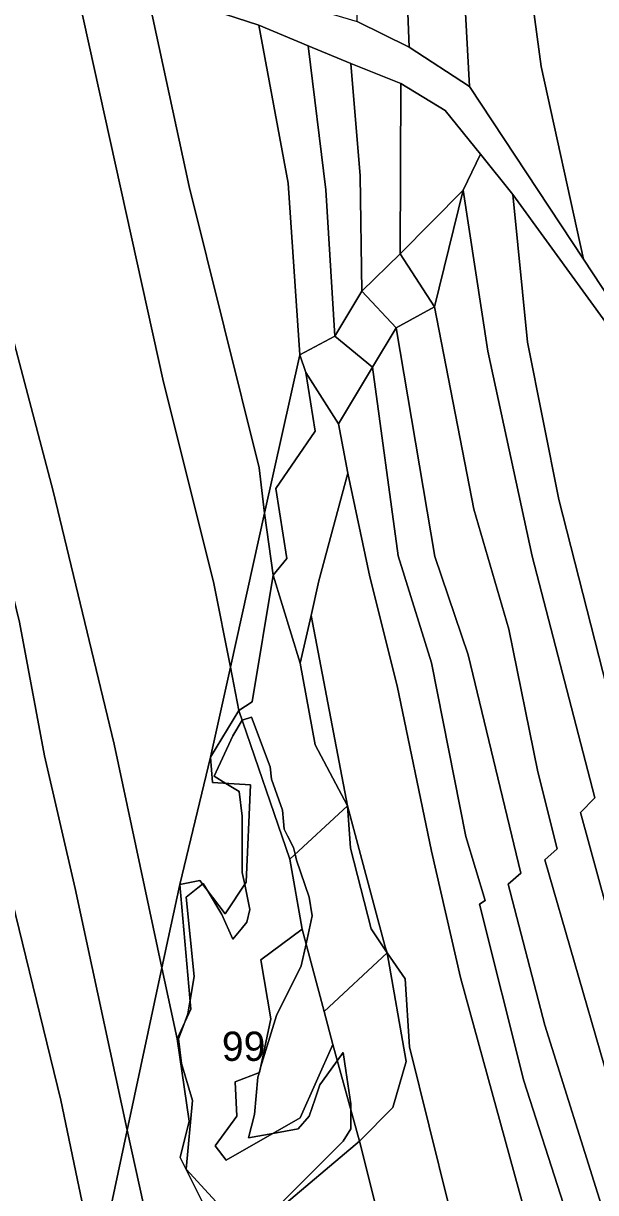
# Model space of a CAD drawing. Extents: x -502026 to -497664, y -1143484 to -1138019.
# Drawn here: x -499377.2 to -499220.8, y -1139831.7 to -1139511.9 of the extents above; entities that cross this region are included whole.
import ezdxf

# ---------------------------------------------------------------- set-up
doc = ezdxf.new("R2010")
doc.units = 0
for name, color, linetype in [('43', 7, 'Continuous'), ('55', 7, 'Continuous'), ('62', 7, 'Continuous'), ('7', 7, 'Continuous')]:
    doc.layers.add(name, color=color, linetype=linetype)

msp = doc.modelspace()

# ---------------------------------------------------------------- linework, layer by layer
at = {"layer": '43'}
msp.add_lwpolyline([(-499291.07, -1139621.36), (-499288.49, -1139634.86), (-499296.45, -1139664.36), (-499298.58, -1139673.8), (-499301.53, -1139686.89), (-499308.96, -1139662.77), (-499305.21, -1139658.22), (-499308.24, -1139639.1), (-499297.44, -1139623.4), (-499300.02, -1139607.4)], close=True, dxfattribs=at)
msp.add_lwpolyline([(-499326.63, -1139837.6), (-499334.36, -1139822.12), (-499331.93, -1139812.11), (-499335.19, -1139789.66), (-499331.44, -1139781.54), (-499334.47, -1139747.41), (-499329.02, -1139746.35), (-499322.04, -1139755.45), (-499316.28, -1139746.81), (-499315.1, -1139720.18), (-499325.49, -1139719.5), (-499326.1, -1139712.6), (-499318.29, -1139699.78), (-499304.37, -1139740.5), (-499301.04, -1139759.66), (-499312.34, -1139768.04), (-499309.61, -1139784.12), (-499312.64, -1139798.84), (-499319.31, -1139801.42), (-499318.86, -1139810.82), (-499324.77, -1139818.86), (-499321.74, -1139822.81), (-499301.57, -1139811.28), (-499292.61, -1139791.22), (-499285.35, -1139817.65), (-499308.24, -1139836.91)], dxfattribs=at)
at = {"layer": '55'}
for points in [[(-499585.34, -1139288.14), (-499562.08, -1139301.27), (-499548.14, -1139313.44), (-499534.96, -1139324.94), (-499524.3, -1139335.07), (-499512.1, -1139346.68), (-499502.1, -1139356.19), (-499492.77, -1139362.7), (-499462.72, -1139386.25), (-499432.97, -1139412.16), (-499404.85, -1139438.08), (-499385.31, -1139457.33), (-499365.03, -1139478.21), (-499347.12, -1139489.91), (-499325.24, -1139498.25), (-499309.82, -1139504.13), (-499296.4, -1139508.21), (-499285.99, -1139511.38), (-499271.78, -1139518.34), (-499255.2, -1139529.15), (-499224.08, -1139576.34), (-499199.1, -1139614.24)], [(-499215.82, -1139596.68), (-499243.36, -1139558.62), (-499252.2, -1139547.66), (-499261.86, -1139535.67), (-499274.05, -1139528.26), (-499287.66, -1139522.83), (-499299.35, -1139517.96), (-499312.87, -1139512.33), (-499343.57, -1139502.35), (-499365.18, -1139490.95), (-499392.27, -1139462.22), (-499414.47, -1139436.01), (-499437.56, -1139413.79), (-499462.13, -1139392.32), (-499482.26, -1139375.44), (-499508.76, -1139357.08), (-499525.43, -1139342.47), (-499537.48, -1139331.9), (-499550.21, -1139319.02), (-499569.54, -1139301.4), (-499573.6, -1139299.19), (-499583.04, -1139294.07)]]:
    msp.add_lwpolyline(points, dxfattribs=at)
for points in [[(-499300.02, -1139607.4), (-499297.44, -1139623.4), (-499308.24, -1139639.1), (-499305.21, -1139658.22), (-499308.96, -1139662.77), (-499311.29, -1139645.86), (-499301.68, -1139602.55)], [(-499308.96, -1139662.77), (-499314.65, -1139697.43), (-499318.29, -1139699.78), (-499320.64, -1139687.98), (-499311.29, -1139645.86)], [(-499301.53, -1139686.89), (-499297.4, -1139709.19), (-499288.62, -1139725.89), (-499304.37, -1139740.5), (-499318.29, -1139699.78), (-499314.65, -1139697.43), (-499308.96, -1139662.77)], [(-499288.62, -1139725.89), (-499297.4, -1139709.19), (-499301.53, -1139686.89), (-499298.58, -1139673.8)], [(-499318.29, -1139699.78), (-499326.1, -1139712.6), (-499320.64, -1139687.98)], [(-499334.47, -1139747.41), (-499326.1, -1139712.6), (-499325.49, -1139719.5), (-499315.1, -1139720.18), (-499316.28, -1139746.81), (-499322.04, -1139755.45), (-499329.02, -1139746.35)], [(-499277.78, -1139766.14), (-499294.97, -1139782.14), (-499301.04, -1139759.66), (-499304.37, -1139740.5), (-499288.62, -1139725.89), (-499287.79, -1139737.48), (-499282.13, -1139759.56)], [(-499277.78, -1139766.14), (-499282.13, -1139759.56), (-499287.79, -1139737.48), (-499288.62, -1139725.89), (-499278.33, -1139764.48)], [(-499335.19, -1139789.66), (-499339.35, -1139770.23), (-499334.47, -1139747.41), (-499331.44, -1139781.54)], [(-499294.97, -1139782.14), (-499292.61, -1139791.22), (-499301.57, -1139811.28), (-499321.74, -1139822.81), (-499324.77, -1139818.86), (-499318.86, -1139810.82), (-499319.31, -1139801.42), (-499312.64, -1139798.84), (-499309.61, -1139784.12), (-499312.34, -1139768.04), (-499301.04, -1139759.66)], [(-499285.35, -1139817.65), (-499292.61, -1139791.22), (-499294.97, -1139782.14), (-499277.78, -1139766.14), (-499272.53, -1139795.8), (-499276.17, -1139808.39)], [(-499335.19, -1139789.66), (-499331.93, -1139812.11), (-499334.36, -1139822.12), (-499326.63, -1139837.6), (-499337.17, -1139850.27), (-499344.29, -1139835.32), (-499348.85, -1139814.64), (-499339.35, -1139770.23)], [(-499344.29, -1139835.32), (-499344.29, -1139851.25), (-499355.29, -1139853.26), (-499357.18, -1139853.6), (-499348.85, -1139814.64)]]:
    msp.add_lwpolyline(points, close=True, dxfattribs=at)
at = {"layer": '62'}
for points in [[(-499306.78, -1139834.62), (-499289.78, -1139817.62), (-499287.66, -1139814.25), (-499287.66, -1139809.25), (-499287.66, -1139807.37), (-499289.03, -1139798.29), (-499289.78, -1139793.37), (-499291.4, -1139795.63), (-499293.07, -1139797.95), (-499296.16, -1139802.25), (-499297.48, -1139806.03), (-499299.12, -1139810.75), (-499302.09, -1139814.25), (-499308.98, -1139815.52), (-499315.69, -1139816.75), (-499314, -1139810.37), (-499313.16, -1139800.12), (-499312.98, -1139799.55), (-499312.78, -1139798.9), (-499312.5, -1139797.94), (-499312.37, -1139797.51), (-499308.06, -1139783.25), (-499301.25, -1139769.62), (-499299.95, -1139763.68), (-499298.28, -1139756), (-499299.12, -1139750.87), (-499302.53, -1139740.75), (-499302.92, -1139739.15), (-499303.37, -1139737.25), (-499304.98, -1139734.12), (-499305.94, -1139732.25), (-499306.1, -1139730.17), (-499306.34, -1139727.12), (-499309.34, -1139718.62), (-499309.75, -1139715.25), (-499314.84, -1139701.62), (-499317.37, -1139702.48), (-499319.94, -1139706.75), (-499325.06, -1139717.75), (-499321.88, -1139719.74), (-499318.25, -1139722), (-499317.41, -1139728.75), (-499317.41, -1139744.12), (-499316.71, -1139747.45), (-499315.28, -1139754.25), (-499316.12, -1139757.75), (-499317.7, -1139759.66), (-499319.94, -1139762.37), (-499322.94, -1139755.62), (-499326.62, -1139749.48), (-499328.03, -1139747.12), (-499328.27, -1139747.32), (-499329.55, -1139748.35), (-499332.69, -1139750.87), (-499330.56, -1139772.62), (-499331.66, -1139779.08), (-499332.28, -1139782.75), (-499333.39, -1139785.76), (-499334.81, -1139789.62), (-499333.97, -1139796.37), (-499331, -1139806.5), (-499332.69, -1139825.25), (-499314.44, -1139845.25)], [(-499314.44, -1139845.25), (-499332.69, -1139825.25), (-499331, -1139806.5), (-499333.97, -1139796.37), (-499334.81, -1139789.62), (-499333.39, -1139785.76), (-499332.28, -1139782.75), (-499331.66, -1139779.08), (-499330.56, -1139772.62), (-499332.69, -1139750.87), (-499329.55, -1139748.35), (-499328.27, -1139747.32), (-499328.03, -1139747.12), (-499326.62, -1139749.48), (-499322.94, -1139755.62), (-499319.94, -1139762.37), (-499317.7, -1139759.66), (-499316.12, -1139757.75), (-499315.28, -1139754.25), (-499316.71, -1139747.45), (-499317.41, -1139744.12), (-499317.41, -1139728.75), (-499318.25, -1139722), (-499321.88, -1139719.74), (-499325.06, -1139717.75), (-499319.94, -1139706.75), (-499317.37, -1139702.48), (-499314.84, -1139701.62), (-499309.75, -1139715.25), (-499309.34, -1139718.62), (-499306.34, -1139727.12), (-499306.1, -1139730.17), (-499305.94, -1139732.25), (-499304.98, -1139734.12), (-499303.37, -1139737.25), (-499302.92, -1139739.15), (-499302.53, -1139740.75), (-499299.12, -1139750.87), (-499298.28, -1139756), (-499299.95, -1139763.68), (-499301.25, -1139769.62), (-499308.06, -1139783.25), (-499312.37, -1139797.51), (-499312.5, -1139797.94), (-499312.78, -1139798.9), (-499312.98, -1139799.55), (-499313.16, -1139800.12), (-499314, -1139810.37), (-499315.69, -1139816.75), (-499308.98, -1139815.52), (-499302.09, -1139814.25), (-499299.12, -1139810.75), (-499297.48, -1139806.03), (-499296.16, -1139802.25), (-499293.07, -1139797.95), (-499291.4, -1139795.63), (-499289.78, -1139793.37), (-499289.03, -1139798.29), (-499287.66, -1139807.37), (-499287.66, -1139809.25), (-499287.66, -1139814.25), (-499289.78, -1139817.62), (-499306.78, -1139834.62)]]:
    msp.add_lwpolyline(points, dxfattribs=at)
at = {"layer": '7'}
for points in [[(-499184.44, -1139632.22), (-499199.1, -1139614.24), (-499224.08, -1139576.34), (-499235.64, -1139523.61), (-499238.66, -1139501.23), (-499241.43, -1139463.52), (-499248.42, -1139418.44), (-499264.05, -1139355.76), (-499283.41, -1139271.78), (-499295.8, -1139226.21), (-499280.37, -1139217.41), (-499264.5, -1139279.38), (-499232, -1139415.17), (-499219.14, -1139483.23), (-499192.99, -1139592.49)], [(-499224.08, -1139576.34), (-499255.2, -1139529.15), (-499257.54, -1139487.26), (-499262.31, -1139442.14), (-499279.52, -1139375.35), (-499296.97, -1139280.67), (-499308.44, -1139229.47), (-499295.8, -1139226.21), (-499283.41, -1139271.78), (-499264.05, -1139355.76), (-499248.42, -1139418.44), (-499241.43, -1139463.52), (-499238.66, -1139501.23), (-499235.64, -1139523.61)], [(-499255.2, -1139529.15), (-499271.78, -1139518.34), (-499272.89, -1139487.91), (-499275.59, -1139453.77), (-499280.27, -1139423.8), (-499287.25, -1139390.3), (-499300.27, -1139320.29), (-499320.87, -1139232.68), (-499308.44, -1139229.47), (-499296.97, -1139280.67), (-499279.52, -1139375.35), (-499262.31, -1139442.14), (-499257.54, -1139487.26)], [(-499271.78, -1139518.34), (-499285.99, -1139511.38), (-499286.22, -1139486.08), (-499289.95, -1139431.87), (-499303.88, -1139361.24), (-499323.12, -1139270.86), (-499332.52, -1139235.5), (-499320.87, -1139232.68), (-499300.27, -1139320.29), (-499287.25, -1139390.3), (-499280.27, -1139423.8), (-499275.59, -1139453.77), (-499272.89, -1139487.91)], [(-499462.13, -1139392.32), (-499452.18, -1139431.77), (-499430, -1139542.05), (-499408.7, -1139631.01), (-499398.52, -1139677.52), (-499366.99, -1139806.44), (-499357.18, -1139853.6), (-499365.9, -1139907.16), (-499375.64, -1139869.1), (-499386.86, -1139810.63), (-499402.82, -1139746.67), (-499404.07, -1139741.68), (-499434.09, -1139621.39), (-499461.83, -1139476.75), (-499476.3, -1139410.22), (-499482.26, -1139375.44)], [(-499437.56, -1139413.79), (-499408.51, -1139551.73), (-499378.3, -1139675.67), (-499371.42, -1139712.23), (-499363.06, -1139748.52), (-499348.85, -1139814.64), (-499357.18, -1139853.6), (-499366.99, -1139806.44), (-499398.52, -1139677.52), (-499408.7, -1139631.01), (-499430, -1139542.05), (-499452.18, -1139431.77), (-499462.13, -1139392.32)], [(-499414.47, -1139436.01), (-499408.53, -1139458.9), (-499399.6, -1139514.37), (-499386.26, -1139575.02), (-499369.1, -1139639.83), (-499352.45, -1139709.04), (-499339.35, -1139770.23), (-499348.85, -1139814.64), (-499363.06, -1139748.52), (-499371.42, -1139712.23), (-499378.3, -1139675.67), (-499408.51, -1139551.73), (-499437.56, -1139413.79)], [(-499365.18, -1139490.95), (-499338.95, -1139609.98), (-499325.28, -1139664.66), (-499320.64, -1139687.98), (-499326.1, -1139712.6), (-499334.47, -1139747.41), (-499339.35, -1139770.23), (-499352.45, -1139709.04), (-499369.1, -1139639.83), (-499386.26, -1139575.02), (-499399.6, -1139514.37), (-499408.53, -1139458.9), (-499414.47, -1139436.01), (-499392.27, -1139462.22)], [(-499343.57, -1139502.35), (-499331.88, -1139556.45), (-499312.72, -1139633.39), (-499311.29, -1139645.86), (-499320.64, -1139687.98), (-499325.28, -1139664.66), (-499338.95, -1139609.98), (-499365.18, -1139490.95)], [(-499312.87, -1139512.33), (-499304.83, -1139555.53), (-499301.68, -1139602.55), (-499311.29, -1139645.86), (-499312.72, -1139633.39), (-499331.88, -1139556.45), (-499343.57, -1139502.35)], [(-499299.35, -1139517.96), (-499294.52, -1139557.38), (-499292.09, -1139597.4), (-499301.68, -1139602.55), (-499304.83, -1139555.53), (-499312.87, -1139512.33)], [(-499287.66, -1139522.83), (-499285.12, -1139553.59), (-499284.66, -1139585.11), (-499292.09, -1139597.4), (-499294.52, -1139557.38), (-499299.35, -1139517.96)], [(-499274.05, -1139528.26), (-499274.16, -1139574.86), (-499284.66, -1139585.11), (-499285.12, -1139553.59), (-499287.66, -1139522.83)], [(-499252.2, -1139547.66), (-499256.96, -1139557.49), (-499274.16, -1139574.86), (-499274.05, -1139528.26), (-499261.86, -1139535.67)], [(-499243.36, -1139558.62), (-499239.42, -1139599.08), (-499230.83, -1139642.06), (-499214.44, -1139706.36), (-499209.67, -1139716.86), (-499209.83, -1139727.05), (-499201.88, -1139768.54), (-499185.97, -1139833.48), (-499171.61, -1139880.27), (-499160.9, -1139922.71), (-499128.96, -1140056.4), (-499142.54, -1140055.34), (-499172.92, -1139921.27), (-499194.67, -1139838.33), (-499224.86, -1139727.73), (-499220.97, -1139723.67), (-499238.15, -1139657.58), (-499250.24, -1139601.55), (-499256.96, -1139557.49), (-499252.2, -1139547.66)], [(-499264.84, -1139589.42), (-499274.16, -1139574.86), (-499256.96, -1139557.49)], [(-499142.54, -1140055.34), (-499154.67, -1140054.94), (-499164.65, -1140012.6), (-499171.01, -1139974.56), (-499179.92, -1139940.65), (-499186.73, -1139912.32), (-499196.49, -1139877.28), (-499202.19, -1139853.04), (-499234.65, -1139740.66), (-499231.31, -1139737.63), (-499236.56, -1139716.62), (-499244.51, -1139677.55), (-499254.06, -1139644.76), (-499264.84, -1139589.42), (-499256.96, -1139557.49), (-499250.24, -1139601.55), (-499238.15, -1139657.58), (-499220.97, -1139723.67), (-499224.86, -1139727.73), (-499194.67, -1139838.33), (-499172.92, -1139921.27)], [(-499215.82, -1139596.68), (-499208.46, -1139633.77), (-499197.99, -1139677.85), (-499190.23, -1139708.81), (-499169.74, -1139776.79), (-499160.99, -1139813.35), (-499148.42, -1139858.6), (-499137.92, -1139908.57), (-499110.87, -1140004.1), (-499100.75, -1140060.46), (-499128.96, -1140056.4), (-499160.9, -1139922.71), (-499171.61, -1139880.27), (-499185.97, -1139833.48), (-499201.88, -1139768.54), (-499209.83, -1139727.05), (-499209.67, -1139716.86), (-499214.44, -1139706.36), (-499230.83, -1139642.06), (-499239.42, -1139599.08), (-499243.36, -1139558.62)], [(-499264.84, -1139589.42), (-499275.3, -1139595.11), (-499284.66, -1139585.11), (-499274.16, -1139574.86)], [(-499275.3, -1139595.11), (-499281.8, -1139605.93), (-499292.09, -1139597.4), (-499284.66, -1139585.11)], [(-499154.67, -1140054.94), (-499168.46, -1140054.39), (-499195.41, -1139929.12), (-499219.22, -1139834.99), (-499234.65, -1139785.92), (-499244.67, -1139747.33), (-499241.17, -1139744.27), (-499255.65, -1139684.59), (-499264.72, -1139657.69), (-499275.3, -1139595.11), (-499264.84, -1139589.42), (-499254.06, -1139644.76), (-499244.51, -1139677.55), (-499236.56, -1139716.62), (-499231.31, -1139737.63), (-499234.65, -1139740.66), (-499202.19, -1139853.04), (-499196.49, -1139877.28), (-499186.73, -1139912.32), (-499179.92, -1139940.65), (-499171.01, -1139974.56), (-499164.65, -1140012.6)], [(-499168.46, -1140054.39), (-499182.39, -1140057.99), (-499186.6, -1140031.86), (-499204.26, -1139941.85), (-499215.89, -1139890.68), (-499229.56, -1139834.82), (-499240.38, -1139801.08), (-499252.55, -1139752.75), (-499250.96, -1139751.79), (-499256.29, -1139734.32), (-499265.67, -1139686.78), (-499274.74, -1139657.5), (-499281.8, -1139605.93), (-499275.3, -1139595.11), (-499264.72, -1139657.69), (-499255.65, -1139684.59), (-499241.17, -1139744.27), (-499244.67, -1139747.33), (-499234.65, -1139785.92), (-499219.22, -1139834.99), (-499195.41, -1139929.12)], [(-499281.8, -1139605.93), (-499291.07, -1139621.36), (-499300.02, -1139607.4), (-499301.68, -1139602.55), (-499292.09, -1139597.4)], [(-499182.39, -1140057.99), (-499196.59, -1140062.55), (-499210.31, -1139968.61), (-499223.35, -1139903.35), (-499238.15, -1139844.22), (-499257.72, -1139772.84), (-499265.67, -1139738.27), (-499274.98, -1139693.06), (-499282.54, -1139663.26), (-499288.49, -1139634.86), (-499291.07, -1139621.36), (-499281.8, -1139605.93), (-499274.74, -1139657.5), (-499265.67, -1139686.78), (-499256.29, -1139734.32), (-499250.96, -1139751.79), (-499252.55, -1139752.75), (-499240.38, -1139801.08), (-499229.56, -1139834.82), (-499215.89, -1139890.68), (-499204.26, -1139941.85), (-499186.6, -1140031.86)], [(-499196.59, -1140062.55), (-499217.66, -1140073.7), (-499244.79, -1139900.32), (-499271.62, -1139791.8), (-499272.84, -1139773.2), (-499277.78, -1139766.14), (-499278.33, -1139764.48), (-499288.62, -1139725.89), (-499298.58, -1139673.8), (-499296.45, -1139664.36), (-499288.49, -1139634.86), (-499282.54, -1139663.26), (-499274.98, -1139693.06), (-499265.67, -1139738.27), (-499257.72, -1139772.84), (-499238.15, -1139844.22), (-499223.35, -1139903.35), (-499210.31, -1139968.61)], [(-499217.66, -1140073.7), (-499237.69, -1140085.86), (-499244.94, -1140038.64), (-499252.47, -1139974.99), (-499257.59, -1139936.39), (-499266.33, -1139893.28), (-499285.35, -1139817.65), (-499276.17, -1139808.39), (-499272.53, -1139795.8), (-499277.78, -1139766.14), (-499272.84, -1139773.2), (-499271.62, -1139791.8), (-499244.79, -1139900.32)], [(-499237.69, -1140085.86), (-499278.75, -1140081.89), (-499300.53, -1139918.49), (-499303.92, -1139898.93), (-499314.46, -1139845.56), (-499308.24, -1139836.91), (-499285.35, -1139817.65), (-499266.33, -1139893.28), (-499257.59, -1139936.39), (-499252.47, -1139974.99), (-499244.94, -1140038.64)]]:
    msp.add_lwpolyline(points, close=True, dxfattribs=at)

# ---------------------------------------------------------------- texts
at = {"layer": '62'}
msp.add_text('99', height=8, dxfattribs=at).set_placement((-499322.95, -1139795.66))

doc.saveas('drawing.dxf')
